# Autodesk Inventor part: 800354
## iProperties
Created: 2007-11
Part Number: 800354
Document SubType Name: Modeling
Designer: RH
Density: 1.06 g/cm^3
Mass: 0.664366 g
Surface Area: 10.9214 cm^2
Volume: 0.626761 cm^3
Material: ABS Plastic
Description: WIRE CLIP
Component Category: Fasteners
Author: RH
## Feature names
1. Extrusion1
2. Extrusion2
3. Extrusion3
